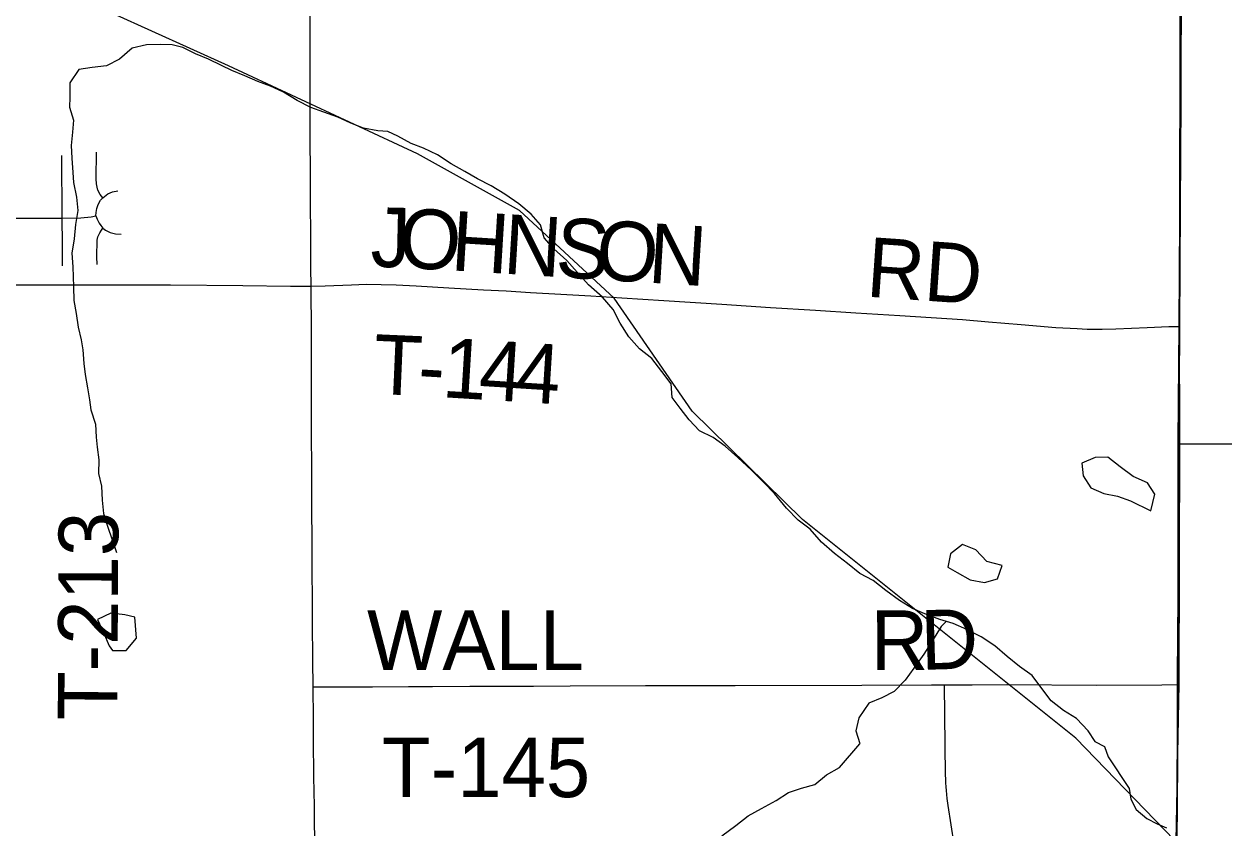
# Model space of a CAD drawing. Extents: x 0 to 34, y -5 to 22.
# Drawn here: x 2.904 to 4.048, y 17.254 to 18.02 of the extents above; entities that cross this region are included whole.
import ezdxf

# ---------------------------------------------------------------- set-up
doc = ezdxf.new("R2010")
doc.units = 0
for name, color, linetype in [('GM_X_City_Street', 7, 'Continuous'), ('GM_X_County_Road', 7, 'Continuous'), ('GM_X_Minor_Lake', 7, 'Continuous'), ('GM_X_Minor_River', 7, 'Continuous'), ('GM_X_Rail_Line', 7, 'Continuous'), ('GM_X_Township_Road', 7, 'Continuous'), ('GM_X_Township_Road_Text', 7, 'Continuous'), ('GM_X_US_Route', 7, 'Continuous'), ('SC_Scratch2', 7, 'Continuous'), ('SH_Cut_Line', 7, 'Continuous')]:
    doc.layers.add(name, color=color, linetype=linetype)

msp = doc.modelspace()

# ---------------------------------------------------------------- linework, layer by layer
at = {"layer": 'GM_X_City_Street'}
for points in [[(2.9412, 17.7896), (2.941, 17.8106), (2.9409, 17.835), (2.9406, 17.8947)], [(2.9796, 17.8542), (2.9771, 17.8575), (2.9749, 17.8617), (2.9741, 17.8644), (2.9736, 17.8676), (2.9732, 17.8725), (2.9734, 17.8978)], [(2.973, 17.8373), (2.9732, 17.8403), (2.9739, 17.8442), (2.9752, 17.848), (2.9773, 17.852), (2.9796, 17.8542), (2.9844, 17.8581), (2.9889, 17.86), (2.9939, 17.8609)], [(2.8955, 17.8349), (2.9409, 17.835), (2.9586, 17.8352), (2.9685, 17.8363), (2.973, 17.8373), (2.9742, 17.834), (2.9762, 17.8301), (2.9775, 17.8279), (2.9795, 17.8254), (2.982, 17.8235), (2.9865, 17.8214), (2.9917, 17.82), (2.9969, 17.8197)], [(2.9741, 17.7909), (2.9739, 17.798), (2.9742, 17.814), (2.9747, 17.8171), (2.9766, 17.8209), (2.9784, 17.8235), (2.9795, 17.8254)]]:
    msp.add_lwpolyline(points, dxfattribs=at)
at = {"layer": 'GM_X_County_Road'}
msp.add_line((4.0053, 17.6199), (4.006, 17.7317), dxfattribs=at)
for points in [[(4.006, 17.7317), (4.0066, 17.8453), (4.0073, 17.9463), (4.0073, 17.9752), (4.0071, 18.0115), (4.0072, 18.0269), (4.0075, 18.0589), (4.0078, 18.0995), (4.0081, 18.1404), (4.0084, 18.1839), (4.0089, 18.2523), (4.009, 18.313), (4.0093, 18.378), (4.0094, 18.3882), (4.0093, 18.3934), (4.0098, 18.5685), (4.0093, 18.903), (4.0096, 18.9356), (4.0094, 18.9697), (4.0092, 19.0147), (4.0095, 19.0414), (4.0094, 19.106)], [(4.0038, 17.3907), (4.0043, 17.4444), (4.0048, 17.4873), (4.0052, 17.5383), (4.0051, 17.5842), (4.0053, 17.6199)], [(4.0053, 17.6199), (4.2003, 17.6201), (4.4006, 17.6192), (4.5493, 17.6189), (4.7099, 17.6182), (4.9463, 17.6177), (5.0601, 17.618)], [(4.0021, 17.0911), (4.0028, 17.1406), (4.0029, 17.1826), (4.003, 17.1952), (4.0036, 17.2488), (4.0037, 17.2604), (4.0038, 17.3788), (4.0038, 17.3907)]]:
    msp.add_lwpolyline(points, dxfattribs=at)
at = {"layer": 'GM_X_Minor_Lake'}
for points in [[(3.9786, 17.5562), (3.9823, 17.572), (3.9754, 17.5829), (3.9616, 17.5889), (3.9493, 17.5982), (3.9375, 17.6072), (3.9253, 17.6071), (3.9128, 17.6016)], [(3.9786, 17.5562), (3.9823, 17.572), (3.9754, 17.5829), (3.9616, 17.5889), (3.9493, 17.5982), (3.9375, 17.6072), (3.9253, 17.6071), (3.9128, 17.6016)], [(3.9128, 17.6016), (3.9141, 17.5895), (3.9211, 17.5781), (3.9337, 17.5726), (3.9466, 17.5701), (3.9592, 17.5656), (3.9786, 17.5562)], [(3.9128, 17.6016), (3.9141, 17.5895), (3.9211, 17.5781), (3.9337, 17.5726), (3.9466, 17.5701), (3.9592, 17.5656), (3.9786, 17.5562)], [(3.8367, 17.5041), (3.8222, 17.5078), (3.8115, 17.519), (3.7989, 17.5242), (3.7876, 17.5153), (3.7851, 17.5024)], [(3.8367, 17.5041), (3.8222, 17.5078), (3.8115, 17.519), (3.7989, 17.5242), (3.7876, 17.5153), (3.7851, 17.5024)], [(3.7851, 17.5024), (3.7938, 17.4975), (3.8061, 17.4904), (3.8198, 17.4879), (3.8323, 17.4915), (3.8367, 17.5041)], [(3.7851, 17.5024), (3.7938, 17.4975), (3.8061, 17.4904), (3.8198, 17.4879), (3.8323, 17.4915), (3.8367, 17.5041)], [(3.0101, 17.4548), (3.0006, 17.4573), (2.9873, 17.4587), (2.9744, 17.4528), (2.9803, 17.4403), (2.9857, 17.4275)], [(3.0101, 17.4548), (3.0006, 17.4573), (2.9873, 17.4587), (2.9744, 17.4528), (2.9803, 17.4403), (2.9857, 17.4275)], [(2.9857, 17.4275), (2.9888, 17.4233), (3.0017, 17.4231), (3.0115, 17.435), (3.0101, 17.4548)], [(2.9857, 17.4275), (2.9888, 17.4233), (3.0017, 17.4231), (3.0115, 17.435), (3.0101, 17.4548)]]:
    msp.add_lwpolyline(points, dxfattribs=at)
at = {"layer": 'GM_X_Minor_River'}
for points in [[(3.9253, 17.3365), (3.9187, 17.3468), (3.9075, 17.3584), (3.8953, 17.3659), (3.8834, 17.3753), (3.8745, 17.387), (3.8653, 17.3994), (3.8534, 17.408), (3.8415, 17.4174), (3.8296, 17.4276), (3.8166, 17.4362), (3.8032, 17.4432), (3.7902, 17.4488), (3.7772, 17.4528), (3.7631, 17.458), (3.7513, 17.4632), (3.739, 17.4707), (3.726, 17.4804), (3.7137, 17.4898), (3.7011, 17.4965), (3.6892, 17.5059), (3.6769, 17.5156), (3.6647, 17.5265), (3.6539, 17.5389), (3.6424, 17.5472), (3.6312, 17.5588), (3.6197, 17.5728), (3.6097, 17.5833), (3.5978, 17.595), (3.5847, 17.607), (3.5728, 17.6179), (3.5613, 17.6262), (3.5483, 17.6325), (3.5383, 17.643), (3.5298, 17.654), (3.5221, 17.6641), (3.5212, 17.6771), (3.5123, 17.6888), (3.5027, 17.7012), (3.4912, 17.7106), (3.4808, 17.7219), (3.4727, 17.7351), (3.4661, 17.748), (3.4557, 17.7597), (3.4426, 17.7713), (3.4318, 17.7834), (3.4218, 17.7947), (3.4095, 17.8056), (3.4003, 17.8161), (3.3967, 17.8286), (3.3879, 17.8388), (3.376, 17.8485), (3.3626, 17.8579), (3.3496, 17.8658), (3.3366, 17.8725), (3.3247, 17.8795), (3.3117, 17.8866), (3.2987, 17.8952), (3.2853, 17.9015), (3.2735, 17.906), (3.2608, 17.9131), (3.2513, 17.9175), (3.2418, 17.9182), (3.2281, 17.9207), (3.2159, 17.9255), (3.2036, 17.9311), (3.1903, 17.9359), (3.1777, 17.9403), (3.1647, 17.947), (3.1517, 17.9548), (3.1394, 17.9608), (3.1272, 17.9652), (3.115, 17.9704), (3.1024, 17.9756), (3.0928, 17.9804), (3.0802, 17.9864), (3.068, 17.9915), (3.0558, 17.9975), (3.0455, 18), (3.0341, 18.0003), (3.0212, 18.0001), (3.0075, 17.9969), (2.9955, 17.9865), (2.983, 17.9799), (2.9693, 17.9783), (2.9568, 17.9766), (2.9482, 17.9639), (2.948, 17.9502), (2.9477, 17.9407), (2.9516, 17.9282), (2.9506, 17.9168), (2.9493, 17.9042), (2.9501, 17.892), (2.9511, 17.8784), (2.9515, 17.8688), (2.9544, 17.8548), (2.9556, 17.8423), (2.9535, 17.8289), (2.9521, 17.8152), (2.95, 17.8015), (2.9509, 17.7886)], [(2.9509, 17.7886), (2.9514, 17.779), (2.9515, 17.7695), (2.952, 17.7566), (2.9541, 17.7441), (2.9561, 17.7312), (2.9589, 17.719), (2.9605, 17.7095), (2.9614, 17.6966), (2.9627, 17.6859), (2.9651, 17.6734), (2.9668, 17.662), (2.968, 17.6525), (2.9727, 17.6389), (2.9733, 17.6263), (2.9741, 17.6168), (2.9758, 17.6047), (2.9755, 17.5917), (2.9783, 17.5796), (2.9789, 17.5663), (2.9801, 17.5537), (2.9841, 17.5416), (2.9927, 17.5166)], [(3.7835, 17.4509), (3.7785, 17.446), (3.7702, 17.4326), (3.762, 17.4196), (3.7527, 17.4065), (3.7444, 17.395), (3.7339, 17.3842), (3.7222, 17.378), (3.7097, 17.3729), (3.7, 17.3591), (3.6972, 17.3466), (3.7011, 17.3345)], [(3.5696, 17.2468), (3.5828, 17.2564), (3.5945, 17.2656), (3.6074, 17.2726), (3.6213, 17.2804), (3.633, 17.2881), (3.6455, 17.292), (3.6581, 17.2956), (3.6694, 17.3048), (3.6818, 17.3118), (3.701, 17.3344)], [(3.9252, 17.3364), (3.9343, 17.3319), (3.9377, 17.3218), (3.9578, 17.2917), (3.9594, 17.2816), (3.9644, 17.2716), (3.9745, 17.2632), (3.9845, 17.2582), (3.9934, 17.2542)]]:
    msp.add_lwpolyline(points, dxfattribs=at)
at = {"layer": 'GM_X_Rail_Line'}
msp.add_lwpolyline([(4.0009, 17.2424), (3.9071, 17.3398), (3.6464, 17.5481), (3.5412, 17.6511), (3.4669, 17.7587), (3.3766, 17.8423), (3.2794, 17.8961), (3.0993, 17.9799), (2.9896, 18.0297), (2.9372, 18.0489)], dxfattribs=at)
at = {"layer": 'GM_X_Township_Road'}
for points in [[(3.178, 17.7702), (3.1779, 17.7876), (3.1778, 17.8057), (3.1776, 17.8622), (3.1775, 17.8794), (3.1773, 17.9094), (3.1773, 17.9465), (3.1771, 18.0037), (3.1769, 18.0683)], [(2.8157, 17.7995), (2.8355, 17.7874), (2.8533, 17.778), (2.8599, 17.7753), (2.865, 17.774), (2.8704, 17.7728), (2.8758, 17.7722), (2.8829, 17.7717), (2.8934, 17.7713), (2.9001, 17.7714), (2.9121, 17.7713), (2.9647, 17.7714), (3.044, 17.7713), (3.1129, 17.7708), (3.1584, 17.7703), (3.1719, 17.7701), (3.178, 17.7702)], [(3.178, 17.7702), (3.1914, 17.7706), (3.2166, 17.7715), (3.2306, 17.772), (3.2448, 17.7719), (3.2593, 17.7715), (3.2781, 17.7706), (3.3093, 17.7687), (3.3423, 17.7668), (3.3641, 17.7656), (3.3871, 17.7641), (3.416, 17.7627), (3.4447, 17.7609), (3.4742, 17.759), (3.5142, 17.7564), (3.5697, 17.753), (3.616, 17.7499), (3.6587, 17.7473), (3.6972, 17.7449), (3.7391, 17.7424), (3.799, 17.7384), (3.8238, 17.7362), (3.8549, 17.7336), (3.8878, 17.7309), (3.9082, 17.7298), (3.9178, 17.7293), (3.9321, 17.7291), (3.9452, 17.7296), (3.9749, 17.7309), (3.9955, 17.7317), (4.006, 17.7317)], [(3.1799, 17.3885), (3.1797, 17.4138), (3.1795, 17.4506), (3.1794, 17.4653), (3.1793, 17.4772), (3.1792, 17.4938), (3.1791, 17.517), (3.179, 17.5338), (3.1789, 17.5523), (3.1786, 17.6737), (3.1784, 17.6992), (3.1783, 17.7255), (3.178, 17.7702)], [(3.1799, 17.3885), (3.2366, 17.3887), (3.2709, 17.3888), (3.2937, 17.3889), (3.3293, 17.3891), (3.3557, 17.3892), (3.3902, 17.3893), (3.4251, 17.3895), (3.4968, 17.3897), (3.5492, 17.3899), (3.5822, 17.39), (3.7031, 17.3903), (3.7694, 17.3905), (3.7817, 17.3905), (3.8082, 17.3906), (3.841, 17.3907), (3.9271, 17.3903), (3.989, 17.3905), (4.0038, 17.3907)], [(3.1823, 17.1638), (3.1822, 17.1886), (3.1818, 17.2155), (3.1815, 17.2463), (3.1814, 17.2576), (3.1812, 17.275), (3.1808, 17.303), (3.1808, 17.3098), (3.1805, 17.3314), (3.1802, 17.358), (3.1799, 17.3885)], [(3.7958, 17.1055), (3.7964, 17.1626), (3.7963, 17.1786), (3.796, 17.1867), (3.7956, 17.1947), (3.7951, 17.2027), (3.7945, 17.2107), (3.7937, 17.2187), (3.7928, 17.2267), (3.7911, 17.2387), (3.7854, 17.2755), (3.7844, 17.2823), (3.784, 17.286), (3.7836, 17.2897), (3.7833, 17.2934), (3.7831, 17.2971), (3.7829, 17.3008), (3.7828, 17.3045), (3.7817, 17.3905)]]:
    msp.add_lwpolyline(points, dxfattribs=at)
at = {"layer": 'GM_X_US_Route'}
for points in [[(4.0095, 18.3868), (4.0056, 17.7327), (4.0045, 17.6221), (4.0045, 17.3912), (4.0018, 17.0912), (4.0007, 17.009), (3.9972, 16.5475), (4.0757, 16.548)], [(4.0018, 17.0912), (4.0045, 17.3912), (4.0045, 17.6221), (4.0056, 17.7327), (4.0095, 18.3868)]]:
    msp.add_lwpolyline(points, dxfattribs=at)
at = {"layer": 'SC_Scratch2'}
msp.add_lwpolyline([(4.0088, 19.1096), (4.0056, 17.7327), (4.0058, 17.6217), (4.0052, 17.3913), (3.9994, 17.0916), (3.9984, 17.0094), (3.9972, 16.5475), (4.0757, 16.548)], dxfattribs=at)
at = {"layer": 'SH_Cut_Line'}
for points in [[(4.0095, 18.3868), (4.0056, 17.7327), (4.0045, 17.6221), (4.0045, 17.3912), (4.0018, 17.0912), (4.0007, 17.009), (3.9972, 16.5475), (4.0757, 16.548)], [(4.0018, 17.0912), (4.0045, 17.3912), (4.0045, 17.6221), (4.0056, 17.7327), (4.0095, 18.3868)]]:
    msp.add_lwpolyline(points, dxfattribs=at)

# ---------------------------------------------------------------- texts
at = {"layer": 'GM_X_Township_Road_Text'}
for s, height, rotation, p in [('J', 0.0568, 358.6953, (3.2344, 17.7887)), ('O', 0.0568, 356.7598, (3.2606, 17.7881)), ('H', 0.0568, 356.4534, (3.3104, 17.7853)), ('N', 0.0568, 356.4552, (3.3603, 17.7822)), ('S', 0.0568, 356.4533, (3.4102, 17.7791)), ('O', 0.0568, 356.457, (3.4485, 17.7767)), ('N', 0.0568, 356.4532, (3.4984, 17.7736)), ('RD', 0.05682, 356.0551, (3.7063, 17.7603)), ('T', 0.0568, 357.4922, (3.2366, 17.6677)), ('1', 0.0568, 356.485, (3.3021, 17.6645)), ('4', 0.0568, 356.4383, (3.337, 17.6624)), ('4', 0.0568, 356.4227, (3.372, 17.6602)), ('-', 0.0568, 356.6413, (3.2789, 17.6659)), ('T-213', 0.05682, 89.7182, (2.9934, 17.3567)), ('WALL', 0.05682, 0, (3.2314, 17.4045)), ('R', 0.0568, 0.16, (3.7115, 17.4045)), ('D', 0.0568, 1.6357, (3.7597, 17.4047)), ('T-145', 0.05682, 0, (3.2456, 17.2835))]:
    msp.add_text(s, height=height, rotation=rotation, dxfattribs=at).set_placement(p)

doc.saveas('drawing.dxf')
